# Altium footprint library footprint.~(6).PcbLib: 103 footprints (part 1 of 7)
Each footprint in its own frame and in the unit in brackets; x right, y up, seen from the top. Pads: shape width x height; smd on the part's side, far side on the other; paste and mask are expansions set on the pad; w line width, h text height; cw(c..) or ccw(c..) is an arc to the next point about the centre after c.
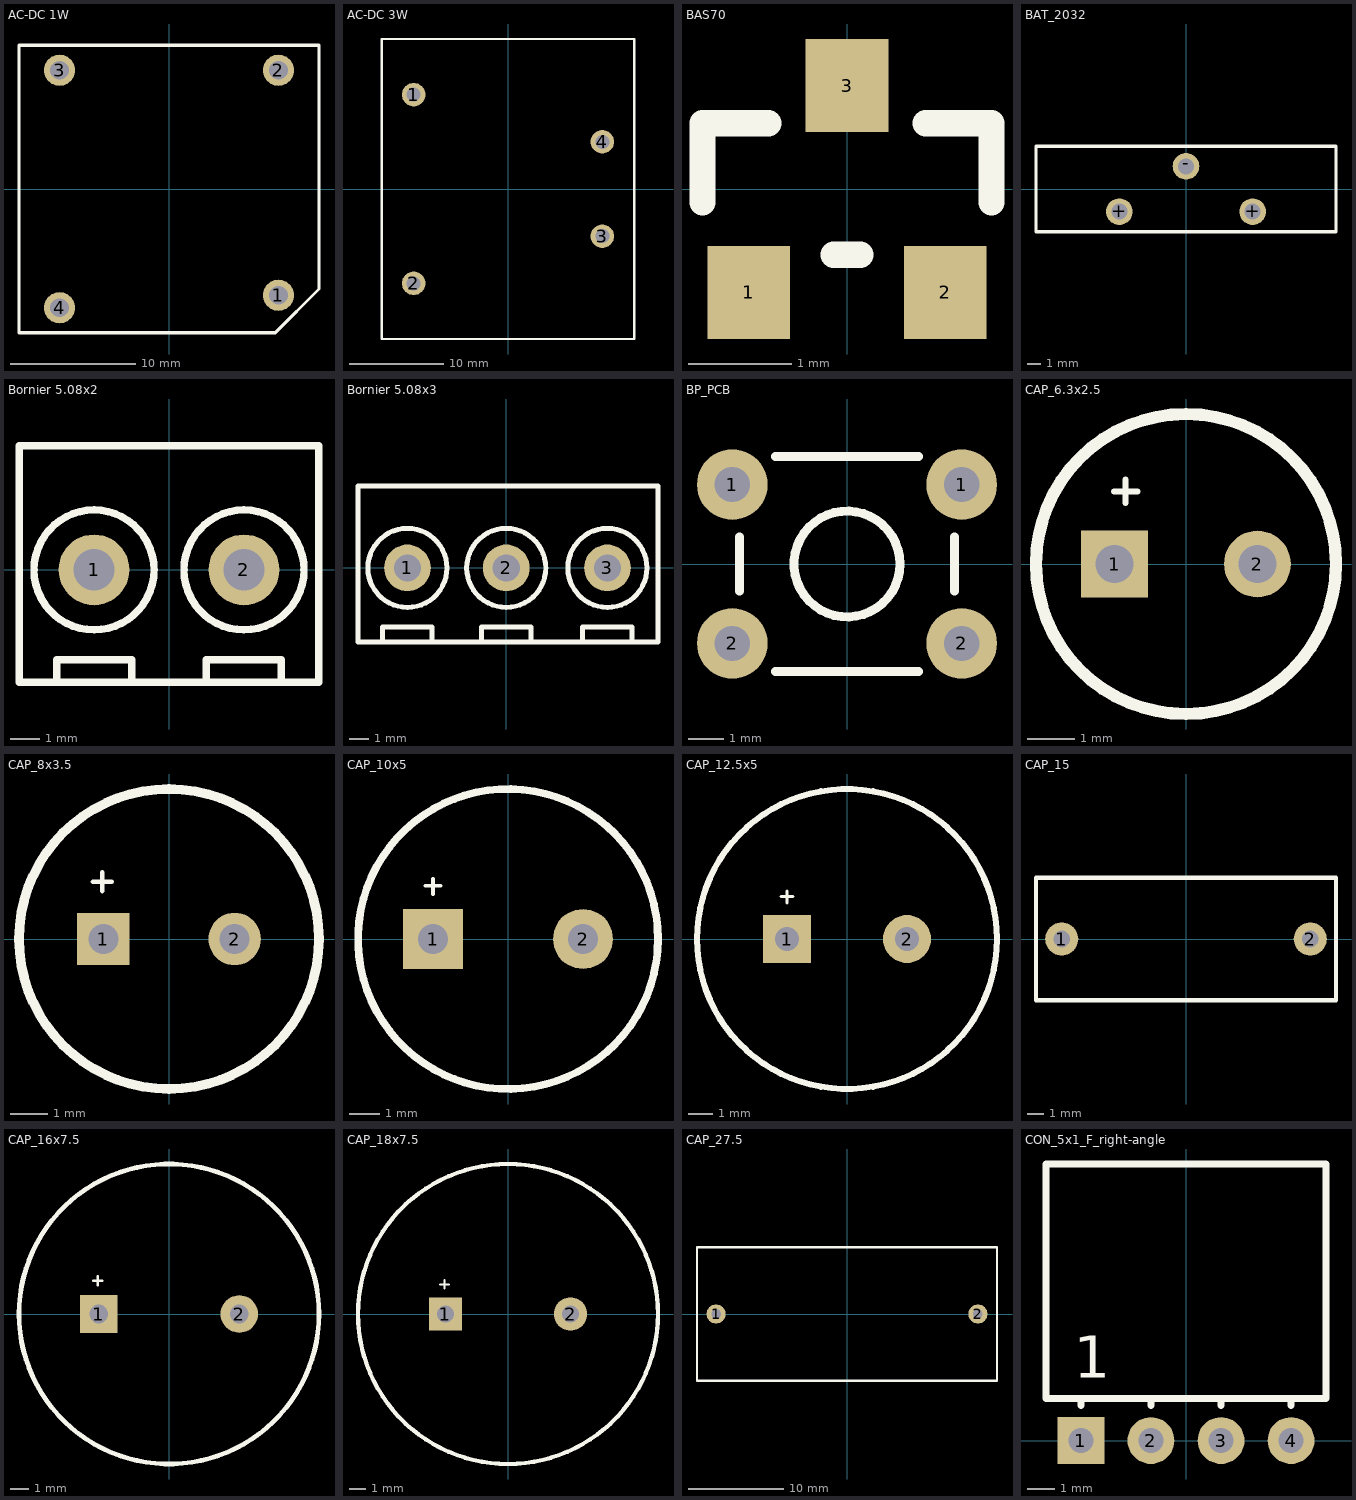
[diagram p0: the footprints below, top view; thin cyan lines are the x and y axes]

## AC-DC 1W [mm]
height 19
pads (4):
  round 2.5 hole 1.5: 1(8.75,-8.5) 2(8.75,9.5) 3(-8.75,9.5) 4(-8.75,-9.5)
Top Overlay:
  lines w0.254: -12,-11.5 -12,11.5 12,11.5 12,-8 8.5,-11.5 -12,-11.5
3D body: height 19, standoff 0, extent -12,-11.5 12,11.5

## AC-DC 3W [mm]
height 19.5
pads (4):
  round 2.5 hole 1.5: 1(-10,10) 2(-10,-10) 3(10,-5) 4(10,5)
Top Overlay:
  lines w0.254: -13.4,-15.9 13.4,-15.9 13.4,15.9 -13.4,15.9 -13.4,-15.9
3D body: height 19.5, standoff 0, extent -13.4,-15.9 13.4,15.9

## BAS70 [mm] "BAS70 SOT23"
height 1
pads (3):
  rect 0.8x0.9 smd: 1(-0.95,-1) 2(0.95,-1) 3(0,1)
Top Overlay:
  lines w0.254: -1.397,-0.127 -1.397,0.635 -0.762,0.635 ; -0.127,-0.635 0.127,-0.635 ; 0.762,0.635 1.397,0.635 1.397,-0.127
3D body: height 1, standoff 0, extent -1.45,-0.65 1.45,0.65

## BAT_2032 [mm] "Battery holder 2032"
height 25
pads (3):
  round 2 hole 1.2: +(-5,-1.7) +(5,-1.7) -(0,1.7)
Top Overlay:
  lines w0.254: -11.25,-3.2 11.25,-3.2 11.25,3.2 -11.25,3.2 -11.25,-3.2
3D body: height 25, standoff 0, extent -11.25,-3.2 11.25,3.2

## Bornier 5.08x2 [mm] "Bornier 5.08x2"
height 10
pads (2):
  round 2.4 hole 1.4: 1(-2.54,0) 2(2.54,0)
Top Overlay:
  circle w0.254: c2.54,0 r2.032
  circle w0.254: c-2.54,0 r2.032
  lines w0.254: -3.81,-3.8 -3.81,-3.048 -1.27,-3.048 -1.27,-3.8 ; 1.27,-3.8 1.27,-3.048 3.81,-3.048 3.81,-3.8 ; -5.08,-3.8 5.08,-3.8 5.08,4.2 -5.08,4.2 -5.08,-3.8

## Bornier 5.08x3 [mm] "Bornier 5.08x3"
height 10
pads (3):
  round 2.4 hole 1.4: 1(-5.08,0) 2(0,0) 3(5.2,0)
Top Overlay:
  circle w0.254: c5.2,0 r2.032
  circle w0.254: c-5.08,0 r2.032
  circle w0.254: c0,0 r2.032
  lines w0.254: -6.35,-3.8 -6.35,-3.048 -3.81,-3.048 -3.81,-3.8 ; -1.27,-3.8 -1.27,-3.048 1.27,-3.048 1.27,-3.8 ; 3.93,-3.8 3.93,-3.048 6.47,-3.048 6.47,-3.8 ; -7.62,-3.8 -7.62,4.2 7.8,4.2 7.8,-3.8 -7.62,-3.8

## BP_PCB [mm] "Mini bouton poussoir sur PCB"
height 5
pads (4):
  round 2 hole 1: 1(-3.25,2.25) 1(3.25,2.25) 2(-3.25,-2.25) 2(3.25,-2.25)
Top Overlay:
  circle w0.254: c0,0 r1.5
  lines w0.254: -3.048,-0.762 -3.048,0.762 ; -2.032,-3.048 2.032,-3.048 ; -2.032,3.048 2.032,3.048 ; 3.048,-0.762 3.048,0.762
3D body: height 1, standoff 0, extent -3.5,-2.75 -3,-1.75
3D body: height 1, standoff 0, extent 3,-2.75 3.5,-1.75
3D body: height 1, standoff 0, extent 3,1.75 3.5,2.75
3D body: height 1, standoff 0, extent -3.5,1.75 -3,2.75
3D body: height 5, standoff 4, extent -1.488,-1.497 1.5,1.497
3D body: height 4, standoff 0, extent -3,-3 3,3

## CAP_6.3x2.5 [mm] "Capacitor throug hole dia=6.3mm, H=11mm, spacing=2.5mm"
height 11
pads (2):
  rect 1.4x1.4 hole 0.8: 1(-1.5,0)
  round 1.4 hole 0.8: 2(1.5,0)
Top Overlay:
  circle w0.254: c0,0 r3.15
  lines w0.127: -1.516,1.524 -1.016,1.524 ; -1.27,1.278 -1.27,1.778
3D body: height 11, standoff 0, extent -3.125,-3.144 3.15,3.144

## CAP_8x3.5 [mm] "Capacitor throug hole dia=8mm, H=12mm, spacing=3.5mm"
height 12
pads (2):
  rect 1.4x1.4 hole 0.8: 1(-1.75,0)
  round 1.4 hole 0.8: 2(1.75,0)
Top Overlay:
  circle w0.254: c0,0 r4
  lines w0.127: -2.024,1.524 -1.524,1.524 ; -1.778,1.278 -1.778,1.778
3D body: height 12, standoff 0, extent -3.968,-3.992 4,3.992

## CAP_10x5 [mm] "Capacitor throug hole dia=10mm, H=16mm, spacing=5mm"
height 16
pads (2):
  rect 2x2 hole 1: 1(-2.5,0)
  round 2 hole 1: 2(2.5,0)
Top Overlay:
  circle w0.254: c0,0 r5
  lines w0.127: -2.75,1.778 -2.25,1.778 ; -2.5,1.5 -2.5,2
3D body: height 16, standoff 0, extent -5,-5 5,5

## CAP_12.5x5 [mm] "Capacitor throug hole dia=12.5mm, H=30mm, spacing=5mm"
height 30
pads (2):
  rect 2x2 hole 1: 1(-2.5,0)
  round 2 hole 1: 2(2.5,0)
Top Overlay:
  circle w0.254: c0,0 r6.25
  lines w0.127: -2.75,1.778 -2.25,1.778 ; -2.5,1.5 -2.5,2
3D body: height 30, standoff 0, extent -6.25,-6.246 6.25,6.246

## CAP_15 [mm] "Film capacitor, step 15mm"
height 0.483
pads (2):
  round 2 hole 1: 1(-7.5,0) 2(7.5,0)
Top Overlay:
  lines w0.254: -9.05,-3.7 9.05,-3.7 9.05,3.7 -9.05,3.7 -9.05,-3.7
3D body: height 19, standoff 0, extent -9.05,-3.7 9.05,3.7

## CAP_16x7.5 [mm] "Capacitor throug hole dia=16mm, H=25mm, spacing=7.5mm"
height 25
pads (2):
  rect 2x2 hole 1: 1(-3.75,0)
  round 2 hole 1: 2(3.75,0)
Top Overlay:
  circle w0.254: c0,0 r8
  lines w0.127: -4.056,1.778 -3.556,1.778 ; -3.81,1.524 -3.81,2.024
3D body: height 25, standoff 0, extent -8,-8 8,8

## CAP_18x7.5 [mm] "Capacitor throug hole dia=18mm, H=35.5mm, spacing=7.5mm"
height 35.5
pads (2):
  rect 2x2 hole 1: 1(-3.75,0)
  round 2 hole 1: 2(3.75,0)
Top Overlay:
  circle w0.254: c0,0 r9
  lines w0.127: -4.064,1.778 -3.556,1.778 ; -3.81,1.524 -3.81,2.024
3D body: height 35.5, standoff 0, extent -9,-9 9,9

## CAP_27.5 [mm] "Film capacitor, step 27.5mm"
height 28
pads (2):
  round 2 hole 1: 1(-13.75,0) 2(13.75,0)
Top Overlay:
  lines w0.254: -15.75,-7 15.75,-7 15.75,7 -15.75,7 -15.75,-7
3D body: height 19, standoff 0, extent -15.75,-7 15.75,7

## CON_5x1_F_right-angle [mm] "step 2.54 SSW-104-02-G-S-RA"
height 2.41
pads (4):
  rect 1.7x1.7 hole 0.9: 1(-3.81,0)
  round 1.7 hole 0.9: 2(-1.27,0) 3(1.27,0) 4(3.81,0)
Top Overlay:
  lines w0.254: -3.81,1.27 -3.81,1.52 ; -1.27,1.27 -1.27,1.52 ; 1.27,1.27 1.27,1.52 ; 3.81,1.27 3.81,1.52 ; -5.08,1.52 -5.08,10.03 5.08,10.03 5.08,1.52 -5.08,1.52
  text "1" at -4.064,2.286 h1.52
3D body: height 1.47, standoff 1.07, extent -4.191,-0.254 -3.429,1.524
3D body: height 2.41, standoff 0, extent -5.08,1.524 5.08,10.033
3D body: height 1.47, standoff 1.07, extent -1.651,-0.254 -0.889,1.524
3D body: height 1.47, standoff 1.07, extent 0.889,-0.254 1.651,1.524
3D body: height 1.47, standoff 1.07, extent 3.429,-0.254 4.191,1.524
